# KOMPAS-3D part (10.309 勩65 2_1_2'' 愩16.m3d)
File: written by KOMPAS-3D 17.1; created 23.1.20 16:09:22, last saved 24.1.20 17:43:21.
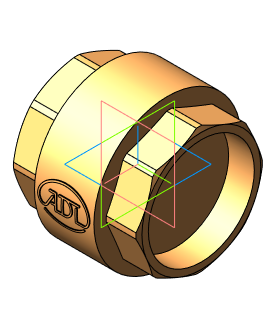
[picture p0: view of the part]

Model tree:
1. Операция без истории:2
